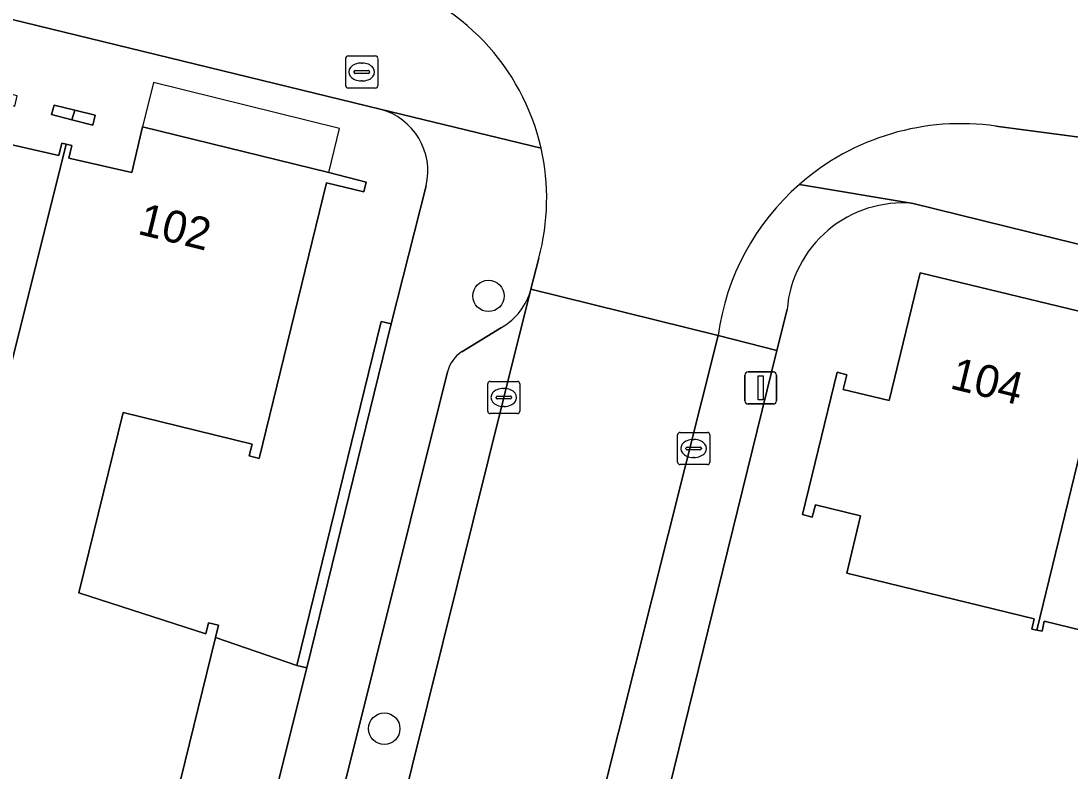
# Model space of a CAD drawing. Extents: x 163266 to 164362, y 381528 to 382286.
# Drawn here: x 163842.38 to 163875.08, y 382141.11 to 382164.49 of the extents above; entities that cross this region are included whole.
import ezdxf

# ---------------------------------------------------------------- set-up
doc = ezdxf.new("R2010")
doc.units = 0
for name, color, linetype in [('IMGEO_Boom', 7, 'Continuous'), ('IMGEO_Brandkraan', 7, 'Continuous'), ('IMGEO_Erf', 7, 'Continuous'), ('IMGEO_Groenvoorziening', 7, 'Continuous'), ('IMGEO_Kolk', 7, 'Continuous'), ('IMGEO_Lichtmast', 7, 'Continuous'), ('IMGEO_Muur', 7, 'Continuous'), ('IMGEO_Pand', 7, 'Continuous'), ('IMGEO_Pand_nummerreeks', 7, 'Continuous'), ('IMGEO_Pand_overbouw', 7, 'Continuous'), ('IMGEO_Parkeervlak_open', 7, 'Continuous'), ('IMGEO_Rijbaan_lokaal_open', 7, 'Continuous'), ('IMGEO_Voetpad_halfverhard', 7, 'Continuous'), ('IMGEO_Voetpad_open', 7, 'Continuous')]:
    doc.layers.add(name, color=color, linetype=linetype)

msp = doc.modelspace()

# ---------------------------------------------------------------- linework, layer by layer
at = {"layer": 'IMGEO_Boom'}
for centre in [(163856.955, 382155.918), (163853.706, 382142.433)]:
    msp.add_circle(centre, 0.489, dxfattribs=at)
at = {"layer": 'IMGEO_Brandkraan'}
for p, q in [((163852.578, 382163.397), (163853.43, 382163.397)), ((163852.503, 382162.471), (163852.503, 382163.323)), ((163852.991, 382163.177), (163853.016, 382163.177)), ((163853.504, 382163.323), (163853.504, 382162.471)), ((163852.762, 382162.891), (163852.762, 382162.903)), ((163853.2, 382162.854), (163852.802, 382162.854)), ((163852.805, 382162.94), (163853.203, 382162.94)), ((163853.246, 382162.903), (163853.246, 382162.891)), ((163853.43, 382162.397), (163852.578, 382162.397)), ((163853.014, 382162.617), (163852.989, 382162.617))]:
    msp.add_line(p, q, dxfattribs=at)
for points in [[(163852.578, 382163.397), (163853.43, 382163.397)], [(163852.503, 382162.471), (163852.503, 382163.323)], [(163853.504, 382163.323), (163853.504, 382162.471)], [(163853.43, 382162.397), (163852.578, 382162.397)]]:
    msp.add_lwpolyline(points, dxfattribs=at)
for centre, radius, start, end in [((163852.58, 382163.321), 0.0765, 91.552, 178.448), ((163852.58, 382163.321), 0.0765, 91.552, 178.448), ((163853.428, 382163.321), 0.0765, 1.552, 88.448), ((163853.428, 382163.321), 0.0765, 1.552, 88.448), ((163852.802, 382162.9), 0.0403, 85.8775, 175.7526), ((163852.799, 382162.89), 0.0366, 178.938, 274.7102), ((163853.203, 382162.897), 0.043, 264.8664, 352.4533), ((163853.207, 382162.902), 0.0386, 1.7309, 96.639), ((163852.58, 382162.473), 0.0765, 181.552, 268.448), ((163852.58, 382162.473), 0.0765, 181.552, 268.448), ((163853.428, 382162.473), 0.0765, 271.552, 358.448), ((163853.428, 382162.473), 0.0765, 271.552, 358.448)]:
    msp.add_arc(centre, radius, start, end, dxfattribs=at)
for centre, major_axis, ratio, start_param, end_param in [((163852.99, 382162.897), (-0.387, 0.002), 0.722429, 4.712389, 7.853982), ((163853.015, 382162.897), (-0.39, 0.002), 0.717154, 1.570796, 4.712389)]:
    msp.add_ellipse(centre, major_axis=major_axis, ratio=ratio, start_param=start_param, end_param=end_param, dxfattribs=at)
at = {"layer": 'IMGEO_Erf'}
for points in [[(163853.576, 382161.738), (163823.589, 382169.051), (163822.215, 382162.822), (163822.521, 382162.755), (163820.755, 382154.748), (163820.449, 382154.815), (163820.14, 382153.413), (163822.567, 382151.602), (163826.062, 382165.81)], [(163841.545, 382160.754), (163843.565, 382160.291), (163843.655, 382160.683), (163843.786, 382160.652), (163843.968, 382160.61), (163843.877, 382160.217), (163845.839, 382159.767), (163846.164, 382161.189), (163851.979, 382159.766), (163853.146, 382159.469), (163853.07, 382159.159), (163851.906, 382159.444), (163849.804, 382150.858), (163849.496, 382150.935), (163849.584, 382151.302), (163845.567, 382152.286), (163844.185, 382146.663), (163848.143, 382145.384), (163848.228, 382145.734), (163848.539, 382145.658), (163848.445, 382145.277), (163850.981, 382144.407), (163853.61, 382155.126), (163853.92, 382155.05), (163855.009, 382159.349)], [(163978.766, 382132.264), (163973.754, 382133.483), (163910.805, 382148.792), (163870.193, 382158.804)], [(163879.947, 382144.397), (163874.278, 382145.781), (163874.211, 382145.468), (163874.054, 382145.501), (163873.897, 382145.535), (163873.971, 382145.853), (163868.129, 382147.281), (163868.557, 382149.069), (163867.146, 382149.41), (163867.045, 382149.023), (163866.742, 382149.105), (163867.821, 382153.541), (163868.129, 382153.463), (163868.012, 382152.998), (163869.443, 382152.659), (163870.41, 382156.639), (163876.26, 382155.221)], [(163866.263, 382155.498), (163865.948, 382154.221), (163861.971, 382138.08), (163867.613, 382136.78), (163868.253, 382139.397), (163872.323, 382138.402), (163871.683, 382135.785), (163874.902, 382135.011), (163875.501, 382137.503)]]:
    msp.add_lwpolyline(points, dxfattribs=at)
msp.add_lwpolyline([(163843.97, 382161.406), (163843.328, 382161.571), (163843.415, 382161.862), (163844.058, 382161.705), (163844.695, 382161.55), (163844.616, 382161.24)], close=True, dxfattribs=at)
for centre, radius, start, end in [((163853.074, 382159.813), 1.99, 346.5295, 75.3839), ((163869.873, 382155.196), 3.622, 84.9253, 175.2172)]:
    msp.add_arc(centre, radius, start, end, dxfattribs=at)
at = {"layer": 'IMGEO_Groenvoorziening'}
msp.add_lwpolyline([(163845.311, 382120.547), (163847.926, 382130.875), (163851.292, 382144.331), (163850.981, 382144.407), (163848.445, 382145.277), (163845.753, 382134.306), (163847.239, 382133.941), (163843.397, 382119.75), (163844.84, 382118.673)], close=True, dxfattribs=at)
at = {"layer": 'IMGEO_Kolk'}
for p, q in [((163857.006, 382153.254), (163857.858, 382153.254)), ((163856.931, 382152.328), (163856.931, 382153.18)), ((163857.419, 382153.034), (163857.444, 382153.034)), ((163857.932, 382153.18), (163857.932, 382152.328)), ((163857.19, 382152.748), (163857.19, 382152.76)), ((163857.628, 382152.711), (163857.23, 382152.711)), ((163857.233, 382152.797), (163857.631, 382152.797)), ((163857.674, 382152.76), (163857.674, 382152.748)), ((163857.858, 382152.254), (163857.006, 382152.254)), ((163857.442, 382152.474), (163857.417, 382152.474)), ((163862.851, 382150.739), (163862.851, 382151.591)), ((163862.926, 382151.665), (163863.778, 382151.665)), ((163863.852, 382151.591), (163863.852, 382150.739)), ((163863.339, 382151.445), (163863.364, 382151.445)), ((163863.11, 382151.159), (163863.11, 382151.171)), ((163863.548, 382151.122), (163863.15, 382151.122)), ((163863.153, 382151.208), (163863.551, 382151.208)), ((163863.594, 382151.171), (163863.594, 382151.159)), ((163863.778, 382150.665), (163862.926, 382150.665)), ((163863.362, 382150.885), (163863.337, 382150.885))]:
    msp.add_line(p, q, dxfattribs=at)
for points in [[(163857.006, 382153.254), (163857.858, 382153.254)], [(163856.931, 382152.328), (163856.931, 382153.18)], [(163857.932, 382153.18), (163857.932, 382152.328)], [(163857.858, 382152.254), (163857.006, 382152.254)], [(163862.851, 382150.739), (163862.851, 382151.591)], [(163862.926, 382151.665), (163863.778, 382151.665)], [(163863.852, 382151.591), (163863.852, 382150.739)], [(163863.778, 382150.665), (163862.926, 382150.665)]]:
    msp.add_lwpolyline(points, dxfattribs=at)
for centre, radius, start, end in [((163857.008, 382153.178), 0.0765, 91.552, 178.448), ((163857.008, 382153.178), 0.0765, 91.552, 178.448), ((163857.856, 382153.178), 0.0765, 1.552, 88.448), ((163857.856, 382153.178), 0.0765, 1.552, 88.448), ((163857.23, 382152.757), 0.0403, 85.8775, 175.7526), ((163857.227, 382152.747), 0.0366, 178.938, 274.7102), ((163857.631, 382152.754), 0.043, 264.8664, 352.4533), ((163857.635, 382152.759), 0.0386, 1.7309, 96.639), ((163857.008, 382152.33), 0.0765, 181.552, 268.448), ((163857.008, 382152.33), 0.0765, 181.552, 268.448), ((163857.856, 382152.33), 0.0765, 271.552, 358.448), ((163857.856, 382152.33), 0.0765, 271.552, 358.448), ((163862.928, 382151.589), 0.0765, 91.552, 178.448), ((163862.928, 382151.589), 0.0765, 91.552, 178.448), ((163863.776, 382151.589), 0.0765, 1.552, 88.448), ((163863.776, 382151.589), 0.0765, 1.552, 88.448), ((163863.15, 382151.168), 0.0403, 85.8775, 175.7526), ((163863.147, 382151.158), 0.0366, 178.938, 274.7102), ((163863.551, 382151.165), 0.043, 264.8664, 352.4533), ((163863.555, 382151.17), 0.0386, 1.7309, 96.639), ((163862.928, 382150.741), 0.0765, 181.552, 268.448), ((163862.928, 382150.741), 0.0765, 181.552, 268.448), ((163863.776, 382150.741), 0.0765, 271.552, 358.448), ((163863.776, 382150.741), 0.0765, 271.552, 358.448)]:
    msp.add_arc(centre, radius, start, end, dxfattribs=at)
for centre, major_axis, ratio, start_param, end_param in [((163857.418, 382152.754), (-0.387, 0.002), 0.722429, 4.712389, 7.853982), ((163857.443, 382152.754), (-0.39, 0.002), 0.717154, 1.570796, 4.712389), ((163863.338, 382151.165), (-0.387, 0.002), 0.722429, 4.712389, 7.853982), ((163863.363, 382151.165), (-0.39, 0.002), 0.717154, 1.570796, 4.712389)]:
    msp.add_ellipse(centre, major_axis=major_axis, ratio=ratio, start_param=start_param, end_param=end_param, dxfattribs=at)
at = {"layer": 'IMGEO_Lichtmast'}
for p, q in [((163865.046, 382153.552), (163865.836, 382153.552)), ((163865.836, 382153.552), (163865.046, 382153.552)), ((163864.946, 382152.652), (163864.946, 382153.452)), ((163864.946, 382153.452), (163864.946, 382152.652)), ((163865.936, 382153.452), (163865.936, 382152.652)), ((163865.936, 382152.652), (163865.936, 382153.452)), ((163865.836, 382152.552), (163865.046, 382152.552)), ((163865.046, 382152.552), (163865.836, 382152.552))]:
    msp.add_line(p, q, dxfattribs=at)
msp.add_lwpolyline([(163865.366, 382153.427), (163865.516, 382153.427), (163865.516, 382152.677), (163865.366, 382152.677), (163865.366, 382153.427)], dxfattribs=at)
for centre, start, end in [((163865.046, 382153.452), 90, 180), ((163865.046, 382153.452), 90, 180), ((163865.836, 382153.452), 0, 90), ((163865.836, 382153.452), 360, 90), ((163865.046, 382152.652), 180, 270), ((163865.046, 382152.652), 180, 270), ((163865.836, 382152.652), 270, 0), ((163865.836, 382152.652), 270, 0)]:
    msp.add_arc(centre, 0.1, start, end, dxfattribs=at)
at = {"layer": 'IMGEO_Muur'}
msp.add_lwpolyline([(163851.292, 382144.331), (163853.92, 382155.05), (163853.61, 382155.126), (163850.981, 382144.407)], close=True, dxfattribs=at)
at = {"layer": 'IMGEO_Pand'}
for points in [[(163833.678, 382162.656), (163830.898, 382151.267), (163837.474, 382148.975), (163835.783, 382142.99), (163835.492, 382141.96), (163838.57, 382139.664), (163838.826, 382140.715), (163840.14, 382146.084), (163843.786, 382160.652), (163843.655, 382160.683), (163843.565, 382160.291), (163841.545, 382160.754), (163841.812, 382161.922), (163842.186, 382161.837), (163842.259, 382162.151), (163841.939, 382162.237), (163836.146, 382163.648), (163835.8, 382162.161)], [(163843.97, 382161.406), (163844.058, 382161.705), (163843.415, 382161.862), (163843.328, 382161.571)], [(163844.058, 382161.705), (163843.97, 382161.406), (163844.616, 382161.24), (163844.695, 382161.55)], [(163838.57, 382139.664), (163840.477, 382138.242), (163845.753, 382134.306), (163848.445, 382145.277), (163848.539, 382145.658), (163848.228, 382145.734), (163848.143, 382145.384), (163844.185, 382146.663), (163845.567, 382152.286), (163849.584, 382151.302), (163849.496, 382150.935), (163849.804, 382150.858), (163851.906, 382159.444), (163853.07, 382159.159), (163853.146, 382159.469), (163851.979, 382159.766), (163846.164, 382161.189), (163845.839, 382159.767), (163843.877, 382160.217), (163843.968, 382160.61), (163843.786, 382160.652), (163840.14, 382146.084), (163838.826, 382140.715)], [(163874.054, 382145.501), (163876.485, 382155.49), (163876.336, 382155.526), (163876.26, 382155.221), (163870.41, 382156.639), (163869.443, 382152.659), (163868.012, 382152.998), (163868.129, 382153.463), (163867.821, 382153.541), (163866.742, 382149.105), (163867.045, 382149.023), (163867.146, 382149.41), (163868.557, 382149.069), (163868.129, 382147.281), (163873.971, 382145.853), (163873.897, 382145.535)], [(163882.231, 382153.763), (163882.077, 382153.802), (163881.833, 382152.799), (163880.523, 382153.119), (163880.766, 382154.119), (163876.56, 382155.145), (163876.642, 382155.452), (163876.485, 382155.49), (163874.054, 382145.501), (163874.211, 382145.468), (163874.278, 382145.781), (163879.947, 382144.397)]]:
    msp.add_lwpolyline(points, close=True, dxfattribs=at)
at = {"layer": 'IMGEO_Pand_overbouw'}
msp.add_lwpolyline([(163851.979, 382159.766), (163852.315, 382161.133), (163846.508, 382162.571), (163846.164, 382161.189)], close=True, dxfattribs=at)
at = {"layer": 'IMGEO_Parkeervlak_open'}
for points in [[(163851.041, 382127.091), (163854.095, 382139.347), (163857.433, 382152.754), (163858.276, 382156.131)], [(163857.361, 382154.938), (163856.128, 382154.182)], [(163855.676, 382153.554), (163849.919, 382130.488)]]:
    msp.add_lwpolyline(points, dxfattribs=at)
for centre, radius, start, end in [((163856.425, 382156.603), 1.911, 299.3428, 345.6826), ((163856.704, 382153.291), 1.062, 122.8829, 165.6285)]:
    msp.add_arc(centre, radius, start, end, dxfattribs=at)
at = {"layer": 'IMGEO_Rijbaan_lokaal_open'}
for points in [[(163872.776, 382161.209), (163875.612, 382160.838), (163876.978, 382166.342), (163875.137, 382166.811)], [(163858.525, 382157.099), (163858.276, 382156.131), (163864.111, 382154.687)], [(163856.421, 382125.172), (163858.041, 382131.11), (163859.65, 382137.006), (163859.972, 382138.187), (163864.111, 382154.687), (163858.276, 382156.131), (163857.433, 382152.754), (163854.095, 382139.347), (163851.041, 382127.091), (163850.313, 382124.17)]]:
    msp.add_lwpolyline(points, dxfattribs=at)
for centre, radius, start, end in [((163851.661, 382158.951), 7.108, 12.7722, 74.4361), ((163871.684, 382153.647), 7.64, 81.7812, 131.2205), ((163851.656, 382158.948), 7.113, 344.9371, 12.7868), ((163871.682, 382153.643), 7.642, 131.1873, 172.1459)]:
    msp.add_arc(centre, radius, start, end, dxfattribs=at)
at = {"layer": 'IMGEO_Voetpad_halfverhard'}
msp.add_lwpolyline([(163865.948, 382154.221), (163864.111, 382154.687), (163859.972, 382138.187), (163859.65, 382137.006), (163861.585, 382136.562), (163861.966, 382138.06), (163861.971, 382138.08)], close=True, dxfattribs=at)
at = {"layer": 'IMGEO_Voetpad_open'}
for points in [[(163816.269, 382172.943), (163801.236, 382176.594), (163800.51, 382174.679), (163823.589, 382169.051), (163853.576, 382161.738), (163858.593, 382160.522)], [(163858.593, 382160.522), (163853.576, 382161.738)], [(163879.061, 382160.378), (163876.345, 382160.746), (163875.612, 382160.838), (163872.776, 382161.209)], [(163855.009, 382159.349), (163853.92, 382155.05), (163851.292, 382144.331), (163847.926, 382130.875), (163845.311, 382120.547), (163844.84, 382118.673), (163876.191, 382095.274), (163880.403, 382092.13), (163921.027, 382061.786), (163923.146, 382060.204), (163930.692, 382054.567), (163932.766, 382053.018), (163933.568, 382052.405), (163935.163, 382049.085), (163931.993, 382041.737), (163930.785, 382038.682)], [(163870.193, 382158.804), (163866.649, 382159.394)], [(163866.649, 382159.394), (163870.193, 382158.804), (163910.805, 382148.792), (163973.754, 382133.483), (163978.766, 382132.264), (163979.399, 382134.355)], [(163858.276, 382156.131), (163858.525, 382157.099)], [(163864.111, 382154.687), (163865.948, 382154.221), (163866.263, 382155.498)], [(163856.128, 382154.182), (163857.361, 382154.938)], [(163849.919, 382130.488), (163855.676, 382153.554)]]:
    msp.add_lwpolyline(points, dxfattribs=at)
for centre, radius, start, end in [((163851.661, 382158.951), 7.108, 12.7722, 74.4361), ((163853.074, 382159.813), 1.99, 346.5295, 75.3839), ((163871.684, 382153.647), 7.64, 81.7812, 131.2205), ((163851.656, 382158.948), 7.113, 344.9371, 12.7868), ((163871.682, 382153.643), 7.642, 131.1873, 172.1459), ((163869.873, 382155.196), 3.622, 84.9253, 175.2172), ((163856.425, 382156.603), 1.911, 299.3428, 345.6826), ((163856.704, 382153.291), 1.062, 122.8829, 165.6285)]:
    msp.add_arc(centre, radius, start, end, dxfattribs=at)

# ---------------------------------------------------------------- texts
at = {"layer": 'IMGEO_Pand_nummerreeks'}
for s, rotation, p in [('102', 346.2493, (163845.982, 382157.856)), ('104', 346.2936, (163871.306, 382153.044))]:
    msp.add_text(s, height=1, rotation=rotation, dxfattribs=at).set_placement(p)

doc.saveas('drawing.dxf')
